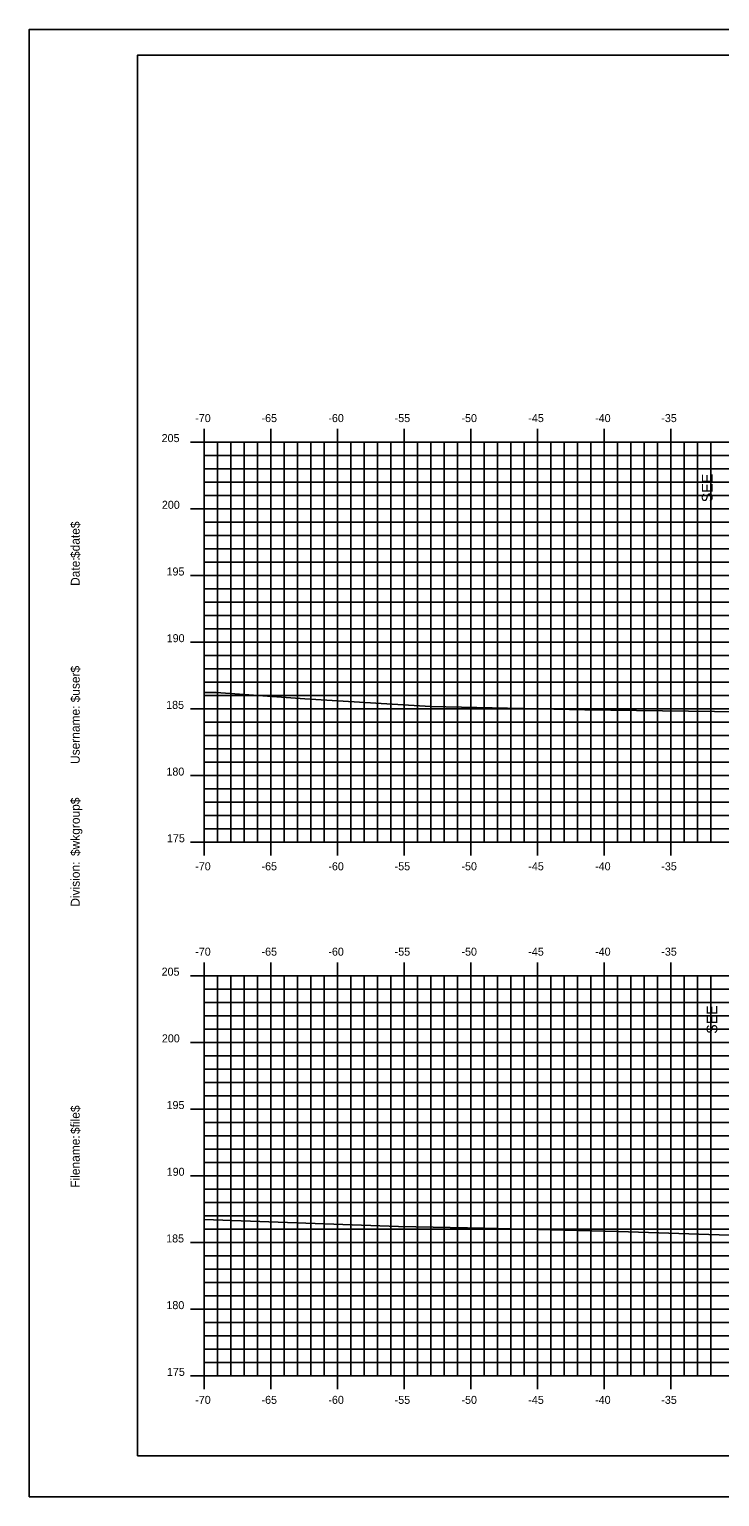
# Model space of a CAD drawing. Extents: x 1724405 to 1724577, y 459560 to 459670.
# Drawn here: x 1724404.9 to 1724456.6, y 459559.6 to 459669.6 of the extents above; entities that cross this region are included whole.
import ezdxf

# ---------------------------------------------------------------- set-up
doc = ezdxf.new("R2010")
doc.units = 0
for name, color, linetype in [('ANNOTATION', 7, 'Continuous'), ('BORDER', 7, 'Continuous'), ('H_V ANNOTATION', 7, 'Continuous'), ('MAJOR', 7, 'Continuous'), ('MINOR', 7, 'Continuous'), ('PLOT BOUNDARY', 7, 'Continuous'), ('S_Roadway_Centerline', 7, 'Continuous')]:
    doc.layers.add(name, color=color, linetype=linetype)

msp = doc.modelspace()

# ---------------------------------------------------------------- linework, layer by layer
at = {"layer": 'BORDER'}
msp.add_lwpolyline([(1724412.99, 459562.61), (1724572.99, 459562.61), (1724572.99, 459667.61), (1724412.99, 459667.61)], close=True, dxfattribs=at)
at = {"layer": 'MAJOR'}
for p, q in [((1724417.99, 459639.61), (1724417.99, 459638.61)), ((1724422.99, 459639.61), (1724422.99, 459638.61)), ((1724427.99, 459639.61), (1724427.99, 459638.61)), ((1724432.99, 459639.61), (1724432.99, 459638.61)), ((1724437.99, 459639.61), (1724437.99, 459638.61)), ((1724442.99, 459639.61), (1724442.99, 459638.61)), ((1724447.99, 459639.61), (1724447.99, 459638.61)), ((1724452.99, 459639.61), (1724452.99, 459638.61)), ((1724416.98, 459638.61), (1724417.99, 459638.61)), ((1724417.99, 459638.61), (1724557.99, 459638.61)), ((1724417.99, 459608.61), (1724417.99, 459638.61)), ((1724417.99, 459608.61), (1724417.99, 459638.61)), ((1724417.99, 459638.61), (1724557.99, 459638.61)), ((1724422.99, 459608.61), (1724422.99, 459638.61)), ((1724427.99, 459608.61), (1724427.99, 459638.61)), ((1724432.99, 459608.61), (1724432.99, 459638.61)), ((1724437.99, 459608.61), (1724437.99, 459638.61)), ((1724442.99, 459608.61), (1724442.99, 459638.61)), ((1724447.99, 459608.61), (1724447.99, 459638.61)), ((1724452.99, 459608.61), (1724452.99, 459638.61)), ((1724416.98, 459633.61), (1724417.99, 459633.61)), ((1724417.99, 459633.61), (1724557.99, 459633.61)), ((1724416.98, 459628.61), (1724417.99, 459628.61)), ((1724417.99, 459628.61), (1724557.99, 459628.61)), ((1724416.98, 459623.61), (1724417.99, 459623.61)), ((1724417.99, 459623.61), (1724557.99, 459623.61)), ((1724416.98, 459618.61), (1724417.99, 459618.61)), ((1724417.99, 459618.61), (1724557.99, 459618.61)), ((1724416.98, 459613.61), (1724417.99, 459613.61)), ((1724417.99, 459613.61), (1724557.99, 459613.61)), ((1724416.98, 459608.61), (1724417.99, 459608.61)), ((1724417.99, 459608.61), (1724557.99, 459608.61)), ((1724417.99, 459608.61), (1724557.99, 459608.61)), ((1724417.99, 459607.61), (1724417.99, 459608.61)), ((1724422.99, 459607.61), (1724422.99, 459608.61)), ((1724427.99, 459607.61), (1724427.99, 459608.61)), ((1724432.99, 459607.61), (1724432.99, 459608.61)), ((1724437.99, 459607.61), (1724437.99, 459608.61)), ((1724442.99, 459607.61), (1724442.99, 459608.61)), ((1724447.99, 459607.61), (1724447.99, 459608.61)), ((1724452.99, 459607.61), (1724452.99, 459608.61)), ((1724417.99, 459599.61), (1724417.99, 459598.61)), ((1724422.99, 459599.61), (1724422.99, 459598.61)), ((1724427.99, 459599.61), (1724427.99, 459598.61)), ((1724432.99, 459599.61), (1724432.99, 459598.61)), ((1724437.99, 459599.61), (1724437.99, 459598.61)), ((1724442.99, 459599.61), (1724442.99, 459598.61)), ((1724447.99, 459599.61), (1724447.99, 459598.61)), ((1724452.99, 459599.61), (1724452.99, 459598.61)), ((1724416.98, 459598.61), (1724417.99, 459598.61)), ((1724417.99, 459598.61), (1724557.99, 459598.61)), ((1724417.99, 459568.61), (1724417.99, 459598.61)), ((1724417.99, 459568.61), (1724417.99, 459598.61)), ((1724417.99, 459598.61), (1724557.99, 459598.61)), ((1724422.99, 459568.61), (1724422.99, 459598.61)), ((1724427.99, 459568.61), (1724427.99, 459598.61)), ((1724432.99, 459568.61), (1724432.99, 459598.61)), ((1724437.99, 459568.61), (1724437.99, 459598.61)), ((1724442.99, 459568.61), (1724442.99, 459598.61)), ((1724447.99, 459568.61), (1724447.99, 459598.61)), ((1724452.99, 459568.61), (1724452.99, 459598.61)), ((1724416.98, 459593.61), (1724417.99, 459593.61)), ((1724417.99, 459593.61), (1724557.99, 459593.61)), ((1724416.98, 459588.61), (1724417.99, 459588.61)), ((1724417.99, 459588.61), (1724557.99, 459588.61)), ((1724416.98, 459583.61), (1724417.99, 459583.61)), ((1724417.99, 459583.61), (1724557.99, 459583.61)), ((1724416.98, 459578.61), (1724417.99, 459578.61)), ((1724417.99, 459578.61), (1724557.99, 459578.61)), ((1724416.98, 459573.61), (1724417.99, 459573.61)), ((1724417.99, 459573.61), (1724557.99, 459573.61)), ((1724416.98, 459568.61), (1724417.99, 459568.61)), ((1724417.99, 459568.61), (1724557.99, 459568.61)), ((1724417.99, 459568.61), (1724557.99, 459568.61)), ((1724417.99, 459567.61), (1724417.99, 459568.61)), ((1724422.99, 459567.61), (1724422.99, 459568.61)), ((1724427.99, 459567.61), (1724427.99, 459568.61)), ((1724432.99, 459567.61), (1724432.99, 459568.61)), ((1724437.99, 459567.61), (1724437.99, 459568.61)), ((1724442.99, 459567.61), (1724442.99, 459568.61)), ((1724447.99, 459567.61), (1724447.99, 459568.61)), ((1724452.99, 459567.61), (1724452.99, 459568.61))]:
    msp.add_line(p, q, dxfattribs=at)
at = {"layer": 'MINOR'}
for p, q in [((1724418.99, 459608.61), (1724418.99, 459638.61)), ((1724419.99, 459608.61), (1724419.99, 459638.61)), ((1724420.99, 459608.61), (1724420.99, 459638.61)), ((1724421.99, 459608.61), (1724421.99, 459638.61)), ((1724423.99, 459608.61), (1724423.99, 459638.61)), ((1724424.99, 459608.61), (1724424.99, 459638.61)), ((1724425.99, 459608.61), (1724425.99, 459638.61)), ((1724426.99, 459608.61), (1724426.99, 459638.61)), ((1724428.99, 459608.61), (1724428.99, 459638.61)), ((1724429.99, 459608.61), (1724429.99, 459638.61)), ((1724430.99, 459608.61), (1724430.99, 459638.61)), ((1724431.99, 459608.61), (1724431.99, 459638.61)), ((1724433.99, 459608.61), (1724433.99, 459638.61)), ((1724434.99, 459608.61), (1724434.99, 459638.61)), ((1724435.99, 459608.61), (1724435.99, 459638.61)), ((1724436.99, 459608.61), (1724436.99, 459638.61)), ((1724438.99, 459608.61), (1724438.99, 459638.61)), ((1724439.99, 459608.61), (1724439.99, 459638.61)), ((1724440.99, 459608.61), (1724440.99, 459638.61)), ((1724441.99, 459608.61), (1724441.99, 459638.61)), ((1724443.99, 459608.61), (1724443.99, 459638.61)), ((1724444.99, 459608.61), (1724444.99, 459638.61)), ((1724445.99, 459608.61), (1724445.99, 459638.61)), ((1724446.99, 459608.61), (1724446.99, 459638.61)), ((1724448.99, 459608.61), (1724448.99, 459638.61)), ((1724449.99, 459608.61), (1724449.99, 459638.61)), ((1724450.99, 459608.61), (1724450.99, 459638.61)), ((1724451.99, 459608.61), (1724451.99, 459638.61)), ((1724453.99, 459608.61), (1724453.99, 459638.61)), ((1724454.99, 459608.61), (1724454.99, 459638.61)), ((1724455.99, 459608.61), (1724455.99, 459638.61)), ((1724417.99, 459637.61), (1724557.99, 459637.61)), ((1724417.99, 459637.61), (1724418.99, 459637.61)), ((1724417.99, 459636.61), (1724557.99, 459636.61)), ((1724417.99, 459636.61), (1724418.99, 459636.61)), ((1724417.99, 459635.61), (1724557.99, 459635.61)), ((1724417.99, 459635.61), (1724418.99, 459635.61)), ((1724417.99, 459634.61), (1724557.99, 459634.61)), ((1724417.99, 459634.61), (1724418.99, 459634.61)), ((1724417.99, 459632.61), (1724557.99, 459632.61)), ((1724417.99, 459632.61), (1724418.99, 459632.61)), ((1724417.99, 459631.61), (1724557.99, 459631.61)), ((1724417.99, 459631.61), (1724418.99, 459631.61)), ((1724417.99, 459630.61), (1724557.99, 459630.61)), ((1724417.99, 459630.61), (1724418.99, 459630.61)), ((1724417.99, 459629.61), (1724557.99, 459629.61)), ((1724417.99, 459629.61), (1724418.99, 459629.61)), ((1724417.99, 459627.61), (1724557.99, 459627.61)), ((1724417.99, 459627.61), (1724418.99, 459627.61)), ((1724417.99, 459626.61), (1724557.99, 459626.61)), ((1724417.99, 459626.61), (1724418.99, 459626.61)), ((1724417.99, 459625.61), (1724557.99, 459625.61)), ((1724417.99, 459625.61), (1724418.99, 459625.61)), ((1724417.99, 459624.61), (1724557.99, 459624.61)), ((1724417.99, 459624.61), (1724418.99, 459624.61)), ((1724417.99, 459622.61), (1724557.99, 459622.61)), ((1724417.99, 459622.61), (1724418.99, 459622.61)), ((1724417.99, 459621.61), (1724557.99, 459621.61)), ((1724417.99, 459621.61), (1724418.99, 459621.61)), ((1724417.99, 459620.61), (1724557.99, 459620.61)), ((1724417.99, 459620.61), (1724418.99, 459620.61)), ((1724417.99, 459619.61), (1724557.99, 459619.61)), ((1724417.99, 459619.61), (1724418.99, 459619.61)), ((1724417.99, 459617.61), (1724557.99, 459617.61)), ((1724417.99, 459617.61), (1724418.99, 459617.61)), ((1724417.99, 459616.61), (1724557.99, 459616.61)), ((1724417.99, 459616.61), (1724418.99, 459616.61)), ((1724417.99, 459615.61), (1724557.99, 459615.61)), ((1724417.99, 459615.61), (1724418.99, 459615.61)), ((1724417.99, 459614.61), (1724557.99, 459614.61)), ((1724417.99, 459614.61), (1724418.99, 459614.61)), ((1724417.99, 459612.61), (1724557.99, 459612.61)), ((1724417.99, 459612.61), (1724418.99, 459612.61)), ((1724417.99, 459611.61), (1724557.99, 459611.61)), ((1724417.99, 459611.61), (1724418.99, 459611.61)), ((1724417.99, 459610.61), (1724557.99, 459610.61)), ((1724417.99, 459610.61), (1724418.99, 459610.61)), ((1724417.99, 459609.61), (1724557.99, 459609.61)), ((1724417.99, 459609.61), (1724418.99, 459609.61)), ((1724417.99, 459597.61), (1724557.99, 459597.61)), ((1724417.99, 459597.61), (1724418.99, 459597.61)), ((1724418.99, 459568.61), (1724418.99, 459598.61)), ((1724419.99, 459568.61), (1724419.99, 459598.61)), ((1724420.99, 459568.61), (1724420.99, 459598.61)), ((1724421.99, 459568.61), (1724421.99, 459598.61)), ((1724423.99, 459568.61), (1724423.99, 459598.61)), ((1724424.99, 459568.61), (1724424.99, 459598.61)), ((1724425.99, 459568.61), (1724425.99, 459598.61)), ((1724426.99, 459568.61), (1724426.99, 459598.61)), ((1724428.99, 459568.61), (1724428.99, 459598.61)), ((1724429.99, 459568.61), (1724429.99, 459598.61)), ((1724430.99, 459568.61), (1724430.99, 459598.61)), ((1724431.99, 459568.61), (1724431.99, 459598.61)), ((1724433.99, 459568.61), (1724433.99, 459598.61)), ((1724434.99, 459568.61), (1724434.99, 459598.61)), ((1724435.99, 459568.61), (1724435.99, 459598.61)), ((1724436.99, 459568.61), (1724436.99, 459598.61)), ((1724438.99, 459568.61), (1724438.99, 459598.61)), ((1724439.99, 459568.61), (1724439.99, 459598.61)), ((1724440.99, 459568.61), (1724440.99, 459598.61)), ((1724441.99, 459568.61), (1724441.99, 459598.61)), ((1724443.99, 459568.61), (1724443.99, 459598.61)), ((1724444.99, 459568.61), (1724444.99, 459598.61)), ((1724445.99, 459568.61), (1724445.99, 459598.61)), ((1724446.99, 459568.61), (1724446.99, 459598.61)), ((1724448.99, 459568.61), (1724448.99, 459598.61)), ((1724449.99, 459568.61), (1724449.99, 459598.61)), ((1724450.99, 459568.61), (1724450.99, 459598.61)), ((1724451.99, 459568.61), (1724451.99, 459598.61)), ((1724453.99, 459568.61), (1724453.99, 459598.61)), ((1724454.99, 459568.61), (1724454.99, 459598.61)), ((1724455.99, 459568.61), (1724455.99, 459598.61)), ((1724417.99, 459596.61), (1724557.99, 459596.61)), ((1724417.99, 459596.61), (1724418.99, 459596.61)), ((1724417.99, 459595.61), (1724557.99, 459595.61)), ((1724417.99, 459595.61), (1724418.99, 459595.61)), ((1724417.99, 459594.61), (1724557.99, 459594.61)), ((1724417.99, 459594.61), (1724418.99, 459594.61)), ((1724417.99, 459592.61), (1724557.99, 459592.61)), ((1724417.99, 459592.61), (1724418.99, 459592.61)), ((1724417.99, 459591.61), (1724557.99, 459591.61)), ((1724417.99, 459591.61), (1724418.99, 459591.61)), ((1724417.99, 459590.61), (1724557.99, 459590.61)), ((1724417.99, 459590.61), (1724418.99, 459590.61)), ((1724417.99, 459589.61), (1724557.99, 459589.61)), ((1724417.99, 459589.61), (1724418.99, 459589.61)), ((1724417.99, 459587.61), (1724557.99, 459587.61)), ((1724417.99, 459587.61), (1724418.99, 459587.61)), ((1724417.99, 459586.61), (1724557.99, 459586.61)), ((1724417.99, 459586.61), (1724418.99, 459586.61)), ((1724417.99, 459585.61), (1724557.99, 459585.61)), ((1724417.99, 459585.61), (1724418.99, 459585.61)), ((1724417.99, 459584.61), (1724557.99, 459584.61)), ((1724417.99, 459584.61), (1724418.99, 459584.61)), ((1724417.99, 459582.61), (1724557.99, 459582.61)), ((1724417.99, 459582.61), (1724418.99, 459582.61)), ((1724417.99, 459581.61), (1724557.99, 459581.61)), ((1724417.99, 459581.61), (1724418.99, 459581.61)), ((1724417.99, 459580.61), (1724557.99, 459580.61)), ((1724417.99, 459580.61), (1724418.99, 459580.61)), ((1724417.99, 459579.61), (1724557.99, 459579.61)), ((1724417.99, 459579.61), (1724418.99, 459579.61)), ((1724417.99, 459577.61), (1724557.99, 459577.61)), ((1724417.99, 459577.61), (1724418.99, 459577.61)), ((1724417.99, 459576.61), (1724557.99, 459576.61)), ((1724417.99, 459576.61), (1724418.99, 459576.61)), ((1724417.99, 459575.61), (1724557.99, 459575.61)), ((1724417.99, 459575.61), (1724418.99, 459575.61)), ((1724417.99, 459574.61), (1724557.99, 459574.61)), ((1724417.99, 459574.61), (1724418.99, 459574.61)), ((1724417.99, 459572.61), (1724557.99, 459572.61)), ((1724417.99, 459572.61), (1724418.99, 459572.61)), ((1724417.99, 459571.61), (1724557.99, 459571.61)), ((1724417.99, 459571.61), (1724418.99, 459571.61)), ((1724417.99, 459570.61), (1724557.99, 459570.61)), ((1724417.99, 459570.61), (1724418.99, 459570.61)), ((1724417.99, 459569.61), (1724557.99, 459569.61)), ((1724417.99, 459569.61), (1724418.99, 459569.61))]:
    msp.add_line(p, q, dxfattribs=at)
at = {"layer": 'PLOT BOUNDARY'}
msp.add_lwpolyline([(1724404.89, 459559.55), (1724574.89, 459559.55), (1724574.89, 459669.55), (1724404.89, 459669.55)], close=True, dxfattribs=at)
at = {"layer": 'S_Roadway_Centerline'}
for points in [[(1724417.99, 459619.85), (1724418.89, 459619.83), (1724425.54, 459619.37), (1724434.97, 459618.78), (1724446.53, 459618.53), (1724460.12, 459618.37), (1724464.54, 459618.49), (1724469.23, 459618.37), (1724479.23, 459618.15), (1724484.8, 459618.1), (1724499.75, 459617.73), (1724508.71, 459617.44), (1724514.19, 459617.49), (1724532.07, 459617.41), (1724536.47, 459617.24), (1724545.7, 459617.02), (1724556.18, 459616.87), (1724557.88, 459616.89), (1724557.99, 459616.9)], [(1724417.99, 459580.32), (1724432.57, 459579.8), (1724439.05, 459579.67), (1724449.05, 459579.44), (1724463.39, 459578.96), (1724466.45, 459578.94), (1724487.3, 459577.78), (1724488.65, 459577.75), (1724491.14, 459577.74), (1724501.67, 459577.9), (1724512.87, 459577.9), (1724513.35, 459577.88), (1724523.87, 459577.87), (1724535, 459577.5), (1724536.23, 459577.43), (1724537.43, 459577.4), (1724557.22, 459577.48), (1724557.99, 459577.46)]]:
    msp.add_lwpolyline(points, dxfattribs=at)

# ---------------------------------------------------------------- texts
at = {"layer": 'ANNOTATION'}
for p in [(1724456.11, 459634.1), (1724456.47, 459594.25)]:
    msp.add_text('SEE', height=0.8, rotation=90, dxfattribs=at).set_placement(p)
at = {"layer": 'BORDER'}
for s, p in [('$date$', (1724408.67, 459629.92)), ('Date:', (1724408.67, 459627.83)), ('$user$', (1724408.67, 459619.1)), ('Username:', (1724408.67, 459614.48)), ('$wkgroup$', (1724408.67, 459607.58)), ('Division:', (1724408.67, 459603.78)), ('$file$', (1724408.67, 459586.74)), ('Filename:', (1724408.67, 459582.71))]:
    msp.add_text(s, height=0.67, rotation=90, dxfattribs=at).set_placement(p)
at = {"layer": 'H_V ANNOTATION'}
for s, p in [('-70', (1724417.33, 459640.11)), ('-65', (1724422.3, 459640.11)), ('-60', (1724427.31, 459640.11)), ('-55', (1724432.28, 459640.11)), ('-50', (1724437.29, 459640.11)), ('-45', (1724442.3, 459640.11)), ('-40', (1724447.31, 459640.11)), ('-35', (1724452.27, 459640.11)), ('205', (1724414.81, 459638.61)), ('200', (1724414.83, 459633.61)), ('195', (1724415.18, 459628.61)), ('190', (1724415.19, 459623.61)), ('185', (1724415.15, 459618.61)), ('180', (1724415.17, 459613.61)), ('175', (1724415.21, 459608.61)), ('-70', (1724417.33, 459606.51)), ('-65', (1724422.3, 459606.51)), ('-60', (1724427.31, 459606.51)), ('-55', (1724432.28, 459606.51)), ('-50', (1724437.29, 459606.51)), ('-45', (1724442.3, 459606.51)), ('-40', (1724447.31, 459606.51)), ('-35', (1724452.27, 459606.51)), ('-70', (1724417.33, 459600.11)), ('-65', (1724422.3, 459600.11)), ('-60', (1724427.31, 459600.11)), ('-55', (1724432.28, 459600.11)), ('-50', (1724437.29, 459600.11)), ('-45', (1724442.3, 459600.11)), ('-40', (1724447.31, 459600.11)), ('-35', (1724452.27, 459600.11)), ('205', (1724414.81, 459598.61)), ('200', (1724414.83, 459593.61)), ('195', (1724415.18, 459588.61)), ('190', (1724415.19, 459583.61)), ('185', (1724415.15, 459578.61)), ('180', (1724415.17, 459573.61)), ('175', (1724415.21, 459568.61)), ('-70', (1724417.33, 459566.51)), ('-65', (1724422.3, 459566.51)), ('-60', (1724427.31, 459566.51)), ('-55', (1724432.28, 459566.51)), ('-50', (1724437.29, 459566.51)), ('-45', (1724442.3, 459566.51)), ('-40', (1724447.31, 459566.51)), ('-35', (1724452.27, 459566.51))]:
    msp.add_text(s, height=0.6, dxfattribs=at).set_placement(p)
at = {"layer": 'MAJOR'}
for p in [(1724417.98, 459608.61), (1724417.98, 459568.61)]:
    msp.add_text('-', height=0.006, dxfattribs=at).set_placement(p)

doc.saveas('drawing.dxf')
